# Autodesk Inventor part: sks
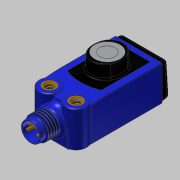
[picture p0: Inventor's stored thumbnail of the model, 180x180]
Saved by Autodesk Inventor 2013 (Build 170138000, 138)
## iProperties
Created: 2007-03
Part Number: sks
Checked By: Alves
Material: nicht zugewiesen
Description: XX BENENNUNG XX
Document SubType Name: Modellieren
Designer: Sienknecht
ME: ST
Title: XX Gruppe XX
Author: Sienknecht
Comments: keine Bemerkung
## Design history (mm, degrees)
sketch "Skizze1"
  geometry: L1 (-8.04, 25.85)-(8.04, 25.85); L2 (8.04, 25.85)-(8.04, 0.593); L3 (-8.04, 25.85)-(-8.04, 0.593); A1 r 4 centre (0, 2.25) between (-1.351, -1.515) and (1.351, -1.515); A2 r 3.54 centre (-4.55, 0) between (-1.351, -1.515) and (-8.04, 0.593); A3 r 3.54 centre (4.55, 0) between (8.04, 0.593) and (1.351, -1.515); 1 further point
  constraints: 6 end point, 6 point on circle, 3 centre point, 3 horizontal alignment, 1 horizontal, 1 parallel, 1 perpendicular, 1 vertical alignment
  dimensions: "d12" = 16.08 distance between parallel lines of L2 L3; "d13" = 8.04 distance from line of point (0, 0) L2; "d20" = 25.85 distance from line of point (0, 0) L1; "d66" = 4 radius of A1; "d67" = 27.6 dimension on A1 L1; "d68" = 9.1 distance of A3.centre A2.centre; "d69" = 3.54 radius of A2; "d70" = 4.55 distance of A3.centre point (0, 0)
extrude "Körper" new body sketch "Skizze1" distance "d8" = 12.1; taper "d9" = 0 deg
sketch "Skizze4"
  geometry: L1 (-5.81, 24.1)-(5.81, 24.1); L2 (5.81, 24.1)-(5.81, 7.35); L3 (-5.81, 24.1)-(-5.81, 7.35); L4 (-8.04, 25.85)-(8.04, 25.85) reference; A1 r 15 centre (0, 21.179) between (-5.81, 7.35) and (5.81, 7.35); 1 further point
  constraints: 6 end point, 2 point on circle, 1 centre point, 1 horizontal, 1 horizontal alignment, 1 parallel, 1 vertical, 1 vertical alignment
  dimensions: "d26" = 11.62 distance between parallel lines of L2 L3; "d27" = 1.75 distance between parallel lines of L1 L4; "d28" = 16.75 distance from line of L2.end L1; "d29" = 15 radius of A1
extrude "Extrusion3" join sketch "Skizze4" distance "d30" = 0.05; taper "d31" = 0 deg
node "Skizze5"
workplane "Arbeitsebene1"
sketch "Skizze6" dims "d26" = 11.62, "d27" = 1.75, "d28" = 16.75, "d29" = 15
  geometry: L1 (0, 15.2)-(3.024, 15.2); L2 (0, 15.2)-(-2.787, 15.2); A1 r 4.5 centre (0, 16.16) between (4.057, 18.107) and (-4.057, 18.107); A2 r 4.5 centre (0, 14.24) between (-4.057, 12.293) and (4.057, 12.293); A3 r 6.718 centre (2, 15.2) between (-4.057, 18.107) and (-4.057, 12.293); A4 r 6.718 centre (-2, 15.2) between (4.057, 12.293) and (4.057, 18.107); 1 further point
  constraints: 8 point on circle, 5 vertical alignment, 4 centre point, 4 end point, 3 tangent, 1 collinear
  dimensions: "d33" = 15.2 distance of point (0, 0) L1.start; "d34" = 5.46 dimension on A1 L2; "d35" = 5.46 dimension on A2 L2; "d36" = 4 distance of A3.centre A4.centre; "d37" = 2 distance of A3.centre L1.start; "d38" = 4.5 radius of A1; "d39" = 0.96 distance of L1.start A1.centre
extrude "Extrusion4" join sketch "Skizze6" distance "d40" = 4.55; taper "d41" = 0 deg
sketch "Skizze7"
  geometry: C1 r 4.35 at (0, 15.2); C2 r 2.65 at (0, 15.2); 1 further point
  constraints: 2 centre point, 1 coincident, 1 vertical alignment
  dimensions: "d42" = 8.7 diameter of C1; "d43" = 15.2 distance of point (0, 0) C1.centre; "d46" = 5.3 diameter of C2
extrude "Extrusion5" cut sketch "Skizze7" distance "d44" = 0.1; taper "d45" = 0 deg
extrude "Extrusion6" cut sketch "Skizze7" distance "d47" = 0.15; taper "d48" = 0 deg
workplane "Arbeitsebene2"
sketch "Skizze8"
  geometry: L1 (-5.81, 24.1)-(5.81, 24.1); L2 (5.81, 24.1)-(5.81, 7.35); L3 (-5.81, 24.1)-(-5.81, 7.35); A1 r 15 centre (0, 21.179) between (-5.81, 7.35) and (5.81, 7.35); A2 r 15 centre (0, 21.179) between (5.81, 7.35) and (8.04, 8.516); A3 r 15 centre (0, 21.179) between (-8.04, 8.516) and (-5.81, 7.35); 1 further point
  constraints: 6 end point, 6 point on circle, 3 centre point, 2 coincident, 2 concentric, 1 horizontal, 1 horizontal alignment, 1 parallel, 1 vertical, 1 vertical alignment
  dimensions: "d50" = 11.62 distance between parallel lines of L2 L3; "d52" = 16.75 distance from line of L2.end L1; "d53" = 15 radius of A1; "d54" = 24.1 distance from line of L1 point (0, 0); "d56" = 8.04 horizontal distance of A3.start A1.centre; "d57" = 8.04 horizontal distance of A1.centre A2.end
workplane "Arbeitsebene3"
sketch "Skizze9"
  geometry: L1 (0, 0)-(-10.833, 0); L2 (-10.833, 0)-(-10.833, -1.188); A1 r 50 centre (0, -50) between (0, 0) and (-10.833, -1.188); 2 further points
  constraints: 4 end point, 2 point on circle, 1 centre point, 1 coincident, 1 horizontal, 1 perpendicular, 1 tangent
  dimensions: "d58" = 1.18767 distance of L1.end L2.end; "d59" = 50 radius of A1
feature "Sweeping1" sketch "Skizze9" dims "d60" = 0
fillet "Rundung1" dims "d73" = 0.2
sketch "Skizze10"
  geometry: C1 r 3.54 at (-4.55, 0); C2 r 3.54 at (4.55, 0); 1 further point
  constraints: 2 centre point, 2 horizontal alignment, 1 equal radius
  dimensions: "d61" = 7.08 diameter of C1; "d62" = 9.1 distance of C2.centre C1.centre; "d63" = 4.55 distance of point (0, 0) C2.centre
extrude "Extrusion7" join sketch "Skizze10" distance "d71" = 12.1; taper "d72" = 0 deg
workplane "Arbeitsebene4"
sketch "Skizze11"
  geometry: C1 r 2.15 at (0, 0); 2 further points
  constraints: 2 horizontal alignment, 1 centre point, 1 coincident
  dimensions: "d75" = 4.3 diameter of C1; "d76" = 4.55 distance of point (4.55, 0) point (0, 0)
extrude "Extrusion8" cut sketch "Skizze11" distance "d77" = 3; taper "d78" = 0 deg
hole "Bohrung1" diameter "d81" = 3.3; stored, may be unused: countersink angle "d85" = 90 deg, drill point angle "d87" = 118 deg; dims "d79" = 10, "d80" = 10, "d82" = 6, "d83" = 4, "d84" = 2, "d86" = 12.1
sketch "Skizze12"
  geometry: C1 r 2.15 at (0, 0); C2 r 1.12 at (0, 0); 1 further point
  constraints: 2 centre point, 1 coincident, 1 horizontal alignment
  dimensions: "d88" = 4.55 distance of point (4.55, 0) C1.centre; "d89" = 4.299 diameter of C1; "d90" = 2.24 diameter of C2
extrude "Extrusion9" join sketch "Skizze12" distance "d91" = 3; taper "d92" = 0 deg
feature "Gewinde1" dims "d93" = 10, "d94" = 0
mirror "Spiegeln2"
chamfer "Fase1" distance "d95" = 0.5; stored, may be unused: second distance "d96" = 2, angle "d97" = 45 deg
workplane "Arbeitsebene5"
sketch "Skizze13"
  geometry: L1 (5.6, 0)-(-5.6, 0); L2 (-5.6, 0)-(-5.137, 5.293); L3 (5.6, 0)-(5.137, 5.293); A1 r 5.157 centre (0, 4.843) between (5.137, 5.293) and (-5.137, 5.293); 1 further point
  constraints: 6 end point, 2 point on circle, 2 tangent, 1 centre point, 1 horizontal, 1 midpoint, 1 vertical alignment
  dimensions: "d99" = 11.2 distance of L1.end L1.start; "d100" = 85 deg angle of L1 L3; "d101" = 85 deg angle of L1 L2; "d102" = 10 dimension on A1 L1
extrude "Extrusion10" join sketch "Skizze13" stored distance "d103" = 3; taper "d104" = 0 deg
workplane "Arbeitsebene6"
sketch "Skizze14"
  geometry: L1 (0, 0)-(0, -18.921); L2 (-4.9, -3.96)-(0, -3.96); L3 (-3.9, -4.96)-(-3.9, -8.746); L4 (-3.9, -8.746)-(-3.25, -8.746); L5 (-3.25, -8.746)-(-3.25, -9.75); L6 (-3.25, -9.75)-(-3.45, -9.75); L7 (-3.45, -9.75)-(-3.275, -11); L8 (-3.275, -11)-(0, -11); L9 (0, -11)-(0, -3.96); A1 r 1 centre (-4.9, -4.96) between (-3.9, -4.96) and (-4.9, -3.96)
  constraints: 18 end point, 3 parallel, 3 perpendicular, 2 point on circle, 2 point on line, 2 tangent, 1 centre point, 1 collinear, 1 vertical
  dimensions: "d106" = 6.5 diameter of L5 L1; "d107" = 6.55 diameter of L7.end L1; "d108" = 6.9 diameter of L6.end L1; "d109" = 7.8 diameter of L3 L1; "d110" = 11 distance from line of L8 L1.start; "d111" = 1 radius of A1; "d112" = 3.96 distance from line of L1.start L2; "d113" = 8.74643 distance from line of L1.start L4; "d114" = 1.25 distance between parallel lines of L6 L8
revolve "Drehung1" sketch "Skizze14" stored, may be unused: angle "d115" = 90 deg
sketch "Skizze15"
  geometry: A1 r 5.157 centre (0, 1.157) between (-4.87, -0.537) and (4.87, -0.537) reference; A2 r 4.9 centre (0, 0) between (-4.87, -0.537) and (4.87, -0.537) reference
extrude "Extrusion11" cut sketch "Skizze15" distance "d116" = 1; taper "d117" = 0 deg
fillet "Rundung2" dims "d118" = 0.2
fillet "Rundung3" dims "d119" = 0.5
feature "Gewinde2" dims "d120" = 10, "d121" = 0
sketch "Skizze16"
  geometry: L1 (27.91, 11.95)-(25.85, 12.004); L2 (25.85, 12.004)-(25.85, 0.1); L3 (27.91, 11.95)-(28.6, 0.663); L4 (0, 0)-(-22.698, 0); A1 r 7 centre (25.85, 7.1) between (25.85, 0.1) and (28.6, 0.663)
  constraints: 8 end point, 2 point on circle, 1 centre point, 1 perpendicular, 1 point on line, 1 vertical
  dimensions: "d122" = 88.5 deg angle of L2 L1; "d123" = 25.85 distance from line of L4.start L2; "d124" = 28.6 horizontal distance of L3.end L4.start; "d125" = 0.1 vertical distance of L2.end L4.start; "d127" = 86.5 deg angle of L3 L4; "d128" = 7 radius of A1; "d129" = 11.9 distance from line of L1 L2.end
extrude "Extrusion12" join sketch "Skizze16" stored distance "d130" = 15.88; taper "d131" = 0 deg
fillet "Rundung4" dims "d132" = 1
workplane "Arbeitsebene7"
sketch "Skizze17"
  geometry: L1 (29.1, 3)-(29.1, 1.799); L2 (0, -2.115)-(0, 21.831) reference; A1 r 1.6 centre (27.5, 1.799) between (27.1, 0.25) and (29.1, 1.799); 1 further point
  constraints: 2 end point, 2 point on circle, 1 centre point, 1 tangent, 1 vertical
  dimensions: "d134" = 3 vertical distance of L1.start point (0, 0); "d135" = 29.1 distance from line of point (0, 0) L1; "d136" = 2 distance from line of A1.start L1; "d137" = 2.75 vertical distance of A1.start L1.start; "d138" = 1.6 radius of A1
workplane "Arbeitsebene8"
sketch "Skizze19"
  geometry: L1 (0.95, -0.688)-(-0.95, -0.688); A1 r 1 centre (0, -1) between (0.95, -0.688) and (-0.95, -0.688); 1 further point
  constraints: 3 point on circle, 2 end point, 1 centre point, 1 horizontal, 1 vertical alignment
  dimensions: "d141" = 1.9 distance of L1.end L1.start; "d142" = 1 radius of A1
feature "Sweeping3" sketch "Skizze19" dims "d143" = 0
workplane "Arbeitsebene9"
mirror "Spiegeln3"
fillet "Rundung5" dims "d145" = 0.3
workplane "Arbeitsebene10"
sketch "Skizze20"
  geometry: L1 (-2.49, 29)-(-4.04, 29); L2 (-4.04, 28)-(-2.49, 28); L3 (-2.49, 28)-(-2.49, 29); L4 (-4.04, 29)-(-4.04, 28); 1 further point
  constraints: 8 end point, 1 horizontal, 1 parallel, 1 vertical
  dimensions: "d149" = 28 distance from line of point (0, 0) L2; "d150" = 1 distance between parallel lines of L2 L1; "d151" = 1.55 distance between parallel lines of L4 L3; "d152" = 2.49 distance from line of point (0, 0) L3
revolve "Drehung2" sketch "Skizze20" stored, may be unused: angle "d153" = 90 deg
sketch "Skizze21"
  geometry: L1 (-2.54, 28.7)-(-3.607, 28.7); L2 (-4.04, 28)-(-2.54, 28); L3 (-2.54, 28)-(-2.54, 28.7); L4 (-4.04, 28.45)-(-4.04, 28); A1 r 0.5 centre (-4.04, 28.95) between (-4.04, 28.45) and (-3.607, 28.7); 1 further point
  constraints: 8 end point, 2 point on circle, 1 centre point, 1 horizontal, 1 parallel, 1 point on line, 1 vertical
  dimensions: "d154" = 28 distance from line of point (0, 0) L2; "d155" = 0.7 distance between parallel lines of L2 L1; "d156" = 1.5 distance between parallel lines of L4 L3; "d157" = 2.54 distance from line of point (0, 0) L3; "d160" = 0.25 vertical distance of L4.start L1.end; "d162" = 0.5 radius of A1
revolve "Drehung3" sketch "Skizze21" stored, may be unused: angle "d161" = 90 deg
workplane "Arbeitsebene11"
sketch "Skizze22"
  geometry: L1 (28.521, 5.7)-(14.899, 5.7); L2 (28.05, 8.956)-(28.05, 7.3); L3 (28.05, 7.3)-(28.75, 7.3); L4 (28.75, 7.3)-(28.75, 7.943); A1 r 1.3 centre (29.342, 9.1) between (28.05, 8.956) and (28.75, 7.943); 1 further point
  constraints: 8 end point, 2 perpendicular, 2 point on circle, 1 centre point, 1 horizontal, 1 parallel
  dimensions: "d164" = 5.7 distance from line of point (0, 0) L1; "d165" = 28.75 horizontal distance of L4.end point (0, 0); "d166" = 0.7 distance between parallel lines of L4 L2; "d167" = 1.6 distance between parallel lines of L3 L1; "d168" = 1.3 radius of A1; "d169" = 0.59197 distance from line of A1.centre L4; "d170" = 1.8 distance from line of L3 A1.centre
revolve "Drehung4" sketch "Skizze22" stored, may be unused: angle "d171" = 110 deg
fillet "Rundung6" dims "d172" = 0.2
fillet "Rundung7" dims "d173" = 0.2
sketch "Skizze23"
  geometry: L1 (7.615, 4.808)-(7.615, 4.558); L2 (7.615, 4.558)-(6.715, 4.558); L3 (6.715, 4.558)-(6.715, 4.808); L4 (6.715, 4.808)-(7.04, 4.808); L5 (7.04, 4.808)-(7.04, 5.858); L6 (7.04, 5.858)-(7.29, 5.858); L7 (7.29, 5.858)-(7.29, 4.808); L8 (7.29, 4.808)-(7.615, 4.808); L9 (6.74, 5.008)-(6.44, 5.008); L10 (6.44, 5.008)-(6.44, 6.008); L11 (6.44, 6.008)-(6.74, 6.008); L12 (6.74, 6.008)-(6.74, 5.008); C1 r 1.35 at (6.94, 5.308); C2 r 1.5 at (6.94, 5.308); 2 further points
  constraints: 24 end point, 9 parallel, 2 centre point, 2 collinear, 2 perpendicular, 1 coincident, 1 vertical, 1 vertical alignment
  dimensions: "d174" = 4 distance of C1.centre point (6.94, 9.308); "d175" = 3 diameter of C2; "d176" = 2.7 diameter of C1; "d179" = 0.25 distance between parallel lines of L5 L7; "d180" = 0.25 distance between parallel lines of L2 L8; "d181" = 0.5 distance from line of L4 C1.centre; "d182" = 1.3 distance between parallel lines of L2 L6; "d183" = 0.1 distance from line of C1.centre L5; "d184" = 0.9 distance between parallel lines of L3 L1; "d185" = 0.5 distance from line of point (6.94, 2.754) L10; "d186" = 0.3 distance between parallel lines of L10 L12; "d187" = 0.3 distance from line of C1.centre L9; "d188" = 1 distance between parallel lines of L9 L11
extrude "Extrusion13" join sketch "Skizze23" distance "d177" = 0.05; taper "d178" = 0 deg
extrude "Extrusion14" join sketch "Skizze23" distance "d189" = 0.05; taper "d190" = 0 deg
hole "Bohrung2" diameter "d193" = 5.8; stored, may be unused: countersink angle "d197" = 90 deg, drill point angle "d199" = 0 deg; dims "d191" = 10, "d192" = 10, "d194" = 6, "d195" = 4, "d196" = 2, "d198" = 5
sketch "Skizze24"
  geometry: C1 r 0.5 at (-1.075, 1.45); C2 r 0.5 at (-1.75, -0.5); 1 further point
  constraints: 2 centre point, 1 equal radius
  dimensions: "d200" = 5.5 vertical distance of C2.centre point (0, -6); "d201" = 7.45 vertical distance of point (0, -6) C1.centre; "d202" = 1 diameter of C2; "d203" = 1.075 horizontal distance of C1.centre point (0, -6); "d204" = 1.75 horizontal distance of point (0, -6) C2.centre
extrude "Extrusion15" join sketch "Skizze24" distance "d205" = 4.6; taper "d206" = 0 deg
fillet "Rundung8" dims "d207" = 0.5
mirror "Spiegeln4"
fillet "Rundung9" dims "d208" = 0.2
fillet "Rundung10" dims "d209" = 0.2
fillet "Rundung11" dims "d210" = 0.3
fillet "Rundung12" dims "d211" = 0.3
fillet "Rundung13" dims "d212" = 0.3
fillet "Rundung14" dims "d213" = 2
fillet "Rundung15" dims "d214" = 0.5
fillet "Rundung16" dims "d215" = 0.5
fillet "Rundung17" dims "d216" = 0.2
node "Volumenkörper1"
node "Volumenkörper"
node "Oberflächenkörper"
node "Projizierte Kontur1"
other parameters: "d32" = 0, "d49" = 0, "d74" = 0, "d98" = -3.96, "d105" = 6, "d133" = -5.05, "d144" = 1.6, "d146" = -5.7, "d163" = 4.04
